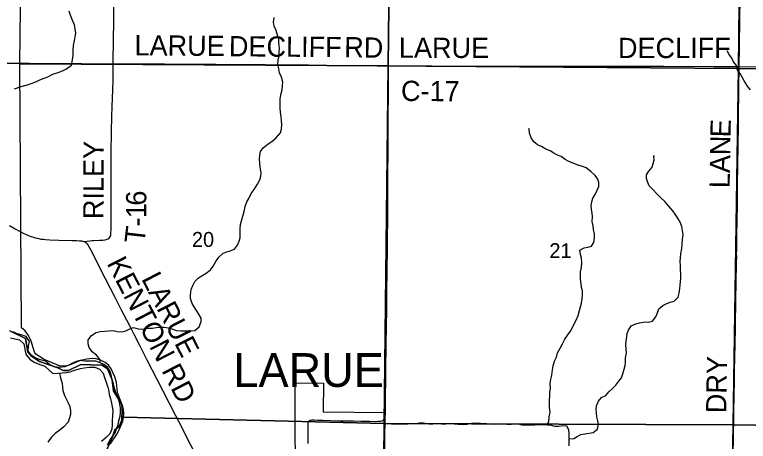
# Model space of a CAD drawing. Extents: x 1584893 to 1934202, y 663575 to 1091909.
# Drawn here: x 1718437 to 1729310, y 942730 to 949050 of the extents above; entities that cross this region are included whole.
import ezdxf

# ---------------------------------------------------------------- set-up
doc = ezdxf.new("R2010")
doc.units = 0
for name, color, linetype in [('GM_X_Corporation', 7, 'Continuous'), ('GM_X_Corporation_Text', 7, 'Continuous'), ('GM_X_County_Road', 7, 'Continuous'), ('GM_X_County_Road_Text', 7, 'Continuous'), ('GM_X_Major_River', 7, 'Continuous'), ('GM_X_Minor_River', 7, 'Continuous'), ('GM_X_Section', 7, 'Continuous'), ('GM_X_Section_Text', 7, 'Continuous'), ('GM_X_State_Route', 7, 'Continuous'), ('GM_X_Township', 7, 'Continuous'), ('GM_X_Township_Road', 7, 'Continuous'), ('GM_X_Township_Road_Text', 7, 'Continuous')]:
    doc.layers.add(name, color=color, linetype=linetype)

msp = doc.modelspace()

# ---------------------------------------------------------------- linework, layer by layer
at = {"layer": 'GM_X_Corporation'}
msp.add_lwpolyline([(1722603, 942161), (1722596, 942851), (1722595, 943595), (1723016, 943590), (1723008, 943168), (1723926, 943158), (1723924, 943078), (1723889, 940900)], dxfattribs=at)
at = {"layer": 'GM_X_County_Road'}
for points in [[(1723973, 948292), (1724028, 948292), (1724323, 948290), (1724536, 948289), (1725160, 948288), (1725635, 948288), (1725980, 948288), (1726258, 948287), (1726537, 948288), (1726849, 948288), (1727226, 948287), (1727521, 948286), (1727685, 948286), (1728063, 948285), (1728801, 948284), (1728981, 948283), (1729174, 948282)], [(1729174, 948282), (1729178, 948282), (1729604, 948276), (1729965, 948272), (1730293, 948266), (1730834, 948258), (1731014, 948255), (1731424, 948249), (1731884, 948243), (1732343, 948236), (1732523, 948235), (1732851, 948230), (1733195, 948225), (1733671, 948219), (1734294, 948211), (1734374, 948210)], [(1718362, 945929), (1718446, 945879), (1718517, 945837), (1718561, 945814), (1718606, 945793), (1718651, 945774), (1718682, 945762), (1718714, 945752), (1718746, 945743), (1718794, 945733), (1718826, 945727), (1718859, 945723), (1718892, 945720), (1718958, 945716), (1719089, 945711), (1719286, 945705), (1719352, 945704), (1719400, 945702), (1719433, 945698), (1719449, 945696), (1719464, 945692), (1719473, 945688)], [(1719473, 945688), (1719478, 945685), (1719491, 945677), (1719502, 945666), (1719512, 945654), (1719521, 945640), (1719561, 945569), (1719599, 945496), (1719709, 945276), (1719919, 944867), (1720015, 944680), (1720092, 944530), (1720152, 944414), (1720207, 944307), (1720287, 944152), (1720397, 943936), (1720542, 943652), (1720720, 943306), (1720820, 943114), (1720917, 942925), (1720999, 942764), (1721082, 942604), (1721194, 942384), (1721271, 942233)]]:
    msp.add_lwpolyline(points, dxfattribs=at)
at = {"layer": 'GM_X_Major_River'}
for points in [[(1718376, 944263), (1718439, 944246), (1718507, 944232), (1718571, 944175), (1718584, 944123), (1718592, 944065), (1718605, 944012), (1718661, 943946), (1718728, 943903), (1718808, 943870), (1718884, 943842), (1718945, 943789), (1719001, 943735), (1719071, 943738), (1719139, 943744), (1719203, 943747), (1719259, 943759), (1719309, 943778), (1719363, 943796), (1719413, 943810), (1719465, 943819), (1719543, 943829), (1719623, 943826), (1719693, 943799), (1719750, 943739), (1719770, 943676), (1719795, 943606), (1719820, 943532), (1719832, 943473), (1719837, 943423), (1719855, 943357), (1719872, 943295), (1719891, 943188), (1719887, 943104), (1719884, 943044), (1719884, 942978), (1719875, 942908), (1719847, 942840), (1719794, 942788), (1719724, 942727)], [(1719815, 942678), (1719856, 942764), (1719927, 942855), (1719953, 942925), (1719970, 942979), (1719982, 943035), (1720001, 943105), (1720007, 943159), (1720006, 943225), (1719992, 943310), (1719973, 943370), (1719938, 943451), (1719920, 943505), (1719901, 943583), (1719883, 943641), (1719872, 943692), (1719854, 943764), (1719811, 943828), (1719757, 943867), (1719705, 943891), (1719642, 943918), (1719590, 943918), (1719538, 943915), (1719476, 943919), (1719408, 943926), (1719350, 943910), (1719296, 943889), (1719242, 943859), (1719179, 943831), (1719097, 943822), (1719024, 943833), (1718954, 943867), (1718892, 943918), (1718821, 943937), (1718753, 943961), (1718683, 944008), (1718636, 944072), (1718644, 944142), (1718655, 944210), (1718608, 944283), (1718550, 944304), (1718466, 944328), (1718414, 944351)]]:
    msp.add_lwpolyline(points, dxfattribs=at)
at = {"layer": 'GM_X_Minor_River'}
for points in [[(1718435, 947952), (1718535, 947984), (1718589, 948000), (1718641, 948015), (1718697, 948035), (1718761, 948061), (1718811, 948083), (1718875, 948111), (1718927, 948131), (1719001, 948167), (1719081, 948195), (1719145, 948220), (1719205, 948248), (1719277, 948302), (1719296, 948380), (1719304, 948446), (1719304, 948521), (1719310, 948595), (1719323, 948661), (1719335, 948721), (1719341, 948777), (1719333, 948841), (1719322, 948901), (1719298, 948954), (1719270, 949026), (1719246, 949102)], [(1722355, 948439), (1722359, 948493), (1722361, 948555), (1722353, 948631), (1722350, 948688), (1722334, 948746), (1722312, 948814), (1722284, 948882), (1722272, 948940), (1722281, 949006)], [(1729343, 947938), (1729298, 947991), (1729249, 948068), (1729220, 948122), (1729189, 948177), (1729150, 948228), (1729135, 948296), (1729090, 948349), (1729065, 948406), (1729025, 948460), (1728996, 948513)], [(1719703, 943892), (1719706, 943935), (1719651, 944005), (1719585, 944055), (1719541, 944120), (1719525, 944176), (1719525, 944232), (1719574, 944300), (1719646, 944342), (1719702, 944358), (1719774, 944363), (1719828, 944365), (1719898, 944371), (1719954, 944359), (1720024, 944353), (1720086, 944368), (1720144, 944396), (1720200, 944414), (1720268, 944396), (1720332, 944392), (1720404, 944404), (1720482, 944407), (1720534, 944415), (1720600, 944419), (1720652, 944421), (1720714, 944413), (1720767, 944394), (1720837, 944374), (1720899, 944366), (1720973, 944366), (1721053, 944366), (1721109, 944371), (1721173, 944427), (1721202, 944503), (1721202, 944553), (1721166, 944616), (1721134, 944668), (1721096, 944724), (1721069, 944774), (1721045, 944845), (1721041, 944899), (1721051, 944981), (1721076, 945037), (1721106, 945095), (1721160, 945151), (1721224, 945191), (1721274, 945221), (1721340, 945271), (1721378, 945327), (1721417, 945393), (1721465, 945459), (1721527, 945515), (1721579, 945535), (1721633, 945554), (1721697, 945578), (1721741, 945634), (1721765, 945696), (1721778, 945746), (1721778, 945821), (1721780, 945877), (1721786, 945941), (1721800, 945997), (1721819, 946065), (1721839, 946133), (1721855, 946207), (1721879, 946277), (1721908, 946327), (1721944, 946399), (1721984, 946462), (1722034, 946538), (1722068, 946604), (1722087, 946656), (1722089, 946706), (1722077, 946792), (1722069, 946854), (1722065, 946904), (1722068, 946970), (1722078, 947025), (1722120, 947076), (1722192, 947138), (1722248, 947170), (1722310, 947220), (1722375, 947300), (1722393, 947356), (1722395, 947424), (1722393, 947479), (1722388, 947539), (1722376, 947605), (1722374, 947671), (1722372, 947731), (1722372, 947803), (1722385, 947882), (1722399, 947936), (1722407, 948000), (1722409, 948052), (1722392, 948126), (1722364, 948190), (1722350, 948250), (1722338, 948319), (1722340, 948377), (1722355, 948439)], [(1726324, 942969), (1726353, 943020), (1726360, 943092), (1726371, 943164), (1726366, 943231), (1726363, 943291), (1726366, 943347), (1726367, 943399), (1726370, 943459), (1726377, 943511), (1726374, 943587), (1726383, 943649), (1726400, 943709), (1726408, 943791), (1726417, 943849), (1726440, 943919), (1726465, 943977), (1726482, 944042), (1726521, 944110), (1726558, 944176), (1726593, 944241), (1726636, 944305), (1726677, 944360), (1726710, 944426), (1726735, 944481), (1726762, 944537), (1726787, 944595), (1726806, 944669), (1726840, 944776), (1726847, 944836), (1726853, 944910), (1726851, 944960), (1726840, 945011), (1726831, 945065), (1726824, 945131), (1726823, 945183), (1726822, 945240), (1726837, 945305), (1726842, 945378), (1726837, 945444), (1726824, 945498), (1726813, 945560), (1726876, 945597), (1726934, 945607), (1726986, 945620), (1727023, 945675), (1727032, 945745), (1727031, 945801), (1727014, 945870), (1727011, 945920), (1726996, 945988), (1727000, 946054), (1726994, 946111), (1726985, 946171), (1726982, 946221), (1726989, 946279), (1727008, 946331), (1727041, 946385), (1727072, 946450), (1727093, 946504), (1727094, 946562), (1727081, 946612), (1727038, 946669), (1726977, 946728), (1726909, 946780), (1726852, 946801), (1726774, 946826), (1726716, 946849), (1726649, 946876), (1726597, 946905), (1726538, 946948), (1726484, 946969), (1726430, 946998), (1726371, 947033), (1726311, 947058), (1726244, 947095), (1726188, 947124), (1726133, 947167), (1726092, 947226), (1726069, 947293), (1726060, 947359), (1726050, 947357)], [(1726655, 942767), (1726723, 942774), (1726776, 942801), (1726826, 942830), (1726885, 942843), (1727013, 942861), (1727074, 942912), (1727089, 942982), (1727078, 943034), (1727065, 943095), (1727060, 943153), (1727057, 943203), (1727060, 943257), (1727089, 943327), (1727136, 943380), (1727200, 943409), (1727241, 943461), (1727292, 943506), (1727345, 943563), (1727390, 943621), (1727429, 943672), (1727448, 943728), (1727469, 943798), (1727484, 943852), (1727489, 943902), (1727492, 943966), (1727503, 944034), (1727498, 944094), (1727493, 944158), (1727498, 944220), (1727509, 944274), (1727514, 944326), (1727535, 944378), (1727576, 944441), (1727642, 944470), (1727698, 944483), (1727783, 944498), (1727833, 944497), (1727891, 944510), (1727938, 944572), (1727965, 944635), (1727986, 944693), (1728041, 944740), (1728094, 944766), (1728152, 944789), (1728210, 944806), (1728269, 944863), (1728284, 944925), (1728294, 944993), (1728300, 945045), (1728305, 945095), (1728312, 945149), (1728309, 945213), (1728304, 945275), (1728303, 945335), (1728300, 945394), (1728305, 945450), (1728312, 945508), (1728325, 945584), (1728330, 945648), (1728336, 945724), (1728343, 945790), (1728336, 945852), (1728327, 945910), (1728298, 945975), (1728267, 946036), (1728226, 946094), (1728192, 946145), (1728128, 946216), (1728071, 946283), (1728013, 946338), (1727954, 946398), (1727901, 946455), (1727842, 946514), (1727821, 946564), (1727802, 946623), (1727803, 946677), (1727834, 946734), (1727885, 946790), (1727902, 946843), (1727913, 946901), (1727909, 946951), (1727918, 946965)], [(1719099, 943740), (1719114, 943670), (1719139, 943587), (1719145, 943535), (1719153, 943481), (1719176, 943408), (1719205, 943350), (1719231, 943298), (1719253, 943247), (1719266, 943183), (1719265, 943125), (1719229, 943015), (1719164, 942943), (1719110, 942900), (1719035, 942848), (1718983, 942793), (1718926, 942717)], [(1723979, 942997), (1724049, 942985), (1724121, 942987), (1724185, 942987), (1724265, 942988), (1724321, 942992), (1724375, 942996), (1724439, 943004), (1724497, 943004), (1724573, 942991), (1724635, 942989), (1724701, 942993), (1724765, 942991), (1724827, 942991), (1724881, 942992), (1724953, 942990), (1725009, 942982), (1725077, 942978), (1725143, 942986), (1725207, 942997), (1725277, 943003), (1725411, 942992)], [(1726653, 942665), (1726657, 942737), (1726653, 942787), (1726656, 942845), (1726651, 942899), (1726622, 942954), (1726562, 942961), (1726496, 942952), (1726446, 942951), (1726394, 942964), (1726334, 942969), (1726268, 942974), (1726216, 942972), (1726146, 942970), (1726094, 942970), (1726028, 942970), (1725956, 942967), (1725902, 942982), (1725850, 942989), (1725796, 942981), (1725729, 942980), (1725677, 942983), (1725623, 942984), (1725557, 942981), (1725495, 942986), (1725431, 942989), (1725411, 942992)]]:
    msp.add_lwpolyline(points, dxfattribs=at)
at = {"layer": 'GM_X_Section'}
for points in [[(1718577, 953608), (1724030, 953572), (1723973, 948294), (1718513, 948322)], [(1724030, 953572), (1729219, 953534), (1729163, 948254), (1723973, 948294)], [(1729219, 953534), (1734432, 953454), (1734388, 948198), (1729163, 948254)], [(1718513, 948322), (1723973, 948294), (1723914, 942992), (1720049, 943086), (1720057, 943138), (1720052, 943202), (1720036, 943254), (1719960, 943451), (1719944, 943601), (1719923, 943685), (1719866, 943806), (1719831, 943854), (1719777, 943899), (1719707, 943933), (1719644, 943954), (1719596, 943958), (1719508, 943949), (1719415, 943928), (1719296, 943878), (1719259, 943862), (1719210, 943850), (1719110, 943841), (1718873, 943944), (1718752, 944021), (1718729, 944053), (1718680, 944216), (1718641, 944300), (1718590, 944369), (1718536, 944413)], [(1723973, 948294), (1729163, 948254), (1729088, 942976), (1723914, 942992)], [(1729163, 948254), (1734388, 948198), (1734314, 942896), (1729088, 942976)]]:
    msp.add_lwpolyline(points, close=True, dxfattribs=at)
for points in [[(1719851, 942688), (1719946, 942827), (1719983, 942892), (1720038, 943028), (1720049, 943086), (1723914, 942992), (1723863, 937892)], [(1723863, 937892), (1723914, 942992), (1729088, 942976), (1729008, 938438)], [(1729316, 938638), (1729277, 938630), (1729255, 938608), (1729209, 938549), (1729120, 938463), (1729088, 938452), (1729008, 938438), (1729088, 942976), (1734314, 942896)]]:
    msp.add_lwpolyline(points, dxfattribs=at)
at = {"layer": 'GM_X_State_Route'}
for points in [[(1723979, 949123), (1723978, 948992), (1723975, 948697), (1723974, 948418), (1723973, 948292)], [(1723973, 948292), (1723973, 948268), (1723972, 948107), (1723970, 947906), (1723970, 947788), (1723969, 947631), (1723968, 947422), (1723968, 947297), (1723967, 947190), (1723967, 947053), (1723966, 946919), (1723965, 946794), (1723964, 946563), (1723962, 946351), (1723962, 946123), (1723961, 945974), (1723959, 945777), (1723956, 945548), (1723953, 945302), (1723951, 945171), (1723949, 945023), (1723946, 944695), (1723942, 944416), (1723938, 944186), (1723936, 944055), (1723935, 943890), (1723933, 943645), (1723930, 943383), (1723926, 943158)], [(1723924, 943078), (1723918, 943065), (1723913, 943057), (1723901, 943045), (1723886, 943034), (1723877, 943031), (1723860, 943026), (1723841, 943023), (1723818, 943022), (1723779, 943020), (1723696, 943022), (1723567, 943024), (1723460, 943027), (1723269, 943031), (1723121, 943034), (1723006, 943038), (1722924, 943040), (1722875, 943042), (1722859, 943042), (1722843, 943041), (1722828, 943040), (1722813, 943036), (1722805, 943033), (1722798, 943028), (1722791, 943019), (1722786, 943009), (1722783, 942999)], [(1723926, 943158), (1723925, 943113), (1723924, 943078)], [(1722783, 942999), (1722782, 942994), (1722780, 942978), (1722780, 942962), (1722781, 942913), (1722782, 942826), (1722783, 942771), (1722783, 942700)]]:
    msp.add_lwpolyline(points, dxfattribs=at)
at = {"layer": 'GM_X_Township'}
for points in [[(1718363, 944365), (1718598, 944251), (1718631, 944058), (1718688, 943990), (1718804, 943910), (1719079, 943820), (1719158, 943779), (1719237, 943778), (1719417, 943868), (1719736, 943858), (1719812, 943804), (1719881, 943642), (1719903, 943476), (1720024, 943273), (1720030, 943209), (1720024, 943042), (1719981, 942947), (1719920, 942898), (1719885, 942796), (1719752, 942495)], [(1719752, 942495), (1719885, 942796), (1719920, 942898), (1719981, 942947), (1720024, 943042), (1720030, 943209), (1720024, 943273), (1719903, 943476), (1719881, 943642), (1719812, 943804), (1719736, 943858), (1719417, 943868), (1719237, 943778), (1719158, 943779), (1719079, 943820), (1718804, 943910), (1718688, 943990), (1718631, 944058), (1718598, 944251), (1718363, 944365)]]:
    msp.add_lwpolyline(points, dxfattribs=at)
at = {"layer": 'GM_X_Township_Road'}
for points in [[(1729174, 948282), (1729174, 948294), (1729174, 948326), (1729178, 948522), (1729179, 948620), (1729183, 948949), (1729187, 949326), (1729188, 949457), (1729188, 949539), (1729189, 949605), (1729190, 949703), (1729190, 949736), (1729190, 949769), (1729190, 949834), (1729191, 949884), (1729193, 950179), (1729194, 950310), (1729195, 950359), (1729196, 950540), (1729197, 950589), (1729198, 950720), (1729199, 950884), (1729200, 950917)], [(1719898, 948324), (1719903, 948707), (1719905, 948920), (1719908, 949166)], [(1715895, 948343), (1715931, 948341), (1715997, 948339), (1716194, 948338), (1716506, 948337), (1716686, 948337), (1716899, 948337), (1717096, 948336), (1717786, 948335), (1717999, 948334), (1718245, 948333), (1718458, 948330), (1718655, 948330), (1718951, 948329), (1719427, 948327), (1719898, 948324)], [(1719473, 945688), (1719513, 945694), (1719553, 945701), (1719580, 945704), (1719613, 945706), (1719695, 945709), (1719744, 945712), (1719777, 945715), (1719794, 945718), (1719810, 945723), (1719825, 945730), (1719838, 945740), (1719848, 945754), (1719856, 945769), (1719860, 945785), (1719862, 945802), (1719865, 945884), (1719866, 945933), (1719866, 946114), (1719866, 946459), (1719865, 946557), (1719865, 946656), (1719866, 946803), (1719869, 947000), (1719873, 947312), (1719879, 947542), (1719884, 947689), (1719892, 947935), (1719895, 948083), (1719898, 948313), (1719898, 948324)], [(1719898, 948324), (1719935, 948324), (1720231, 948322), (1720461, 948321), (1720658, 948321), (1721018, 948319), (1721166, 948320), (1721675, 948314), (1721921, 948312), (1722151, 948311), (1722331, 948309), (1722479, 948306), (1722676, 948306), (1722791, 948305), (1723184, 948299), (1723496, 948297), (1723660, 948295), (1723808, 948294), (1723973, 948292)], [(1729121, 944590), (1729123, 944685), (1729127, 944898), (1729130, 945013), (1729132, 945170), (1729134, 945285), (1729136, 945377), (1729138, 945472), (1729137, 945505), (1729139, 945570), (1729142, 945784), (1729148, 946227), (1729151, 946555), (1729155, 946801), (1729160, 947129), (1729163, 947392), (1729166, 947605), (1729170, 947851), (1729169, 947933), (1729169, 947982), (1729170, 948032), (1729174, 948212), (1729174, 948261), (1729174, 948282)], [(1729095, 943015), (1729097, 943126), (1729097, 943175), (1729105, 943635), (1729107, 943799), (1729110, 943946), (1729115, 944193), (1729119, 944389), (1729121, 944553), (1729121, 944590)], [(1723912, 942213), (1723913, 942295), (1723916, 942409), (1723917, 942622), (1723921, 942852), (1723922, 942949), (1723924, 943078)], [(1729054, 940378), (1729054, 940454), (1729054, 940518), (1729057, 940716), (1729059, 940896), (1729061, 941009), (1729064, 941208), (1729067, 941415), (1729069, 941504), (1729075, 941751), (1729077, 941855), (1729079, 942002), (1729081, 942152), (1729084, 942303), (1729086, 942473), (1729087, 942572), (1729088, 942621), (1729089, 942703), (1729090, 942802), (1729091, 942868), (1729095, 943015)]]:
    msp.add_lwpolyline(points, dxfattribs=at)

# ---------------------------------------------------------------- texts
at = {"layer": 'GM_X_Corporation_Text'}
msp.add_text('LARUE', height=500, rotation=0, dxfattribs=at).set_placement((1721679, 943536))
at = {"layer": 'GM_X_County_Road_Text'}
for s, rotation, p in [('LARUE', 359.7964, (1724131, 948412)), ('DECLIFF', 0, (1727378, 948407)), ('C-17', 359.6489, (1724162, 947772)), ('KENTON RD', 297.0983, (1719797, 945368)), ('LARUE', 297.1122, (1720310, 945139))]:
    msp.add_text(s, height=300, rotation=rotation, dxfattribs=at).set_placement(p)
at = {"layer": 'GM_X_Section_Text'}
for s, p in [('20', (1721064, 945610)), ('21', (1726362, 945444))]:
    msp.add_text(s, height=221, rotation=0, dxfattribs=at).set_placement(p)
at = {"layer": 'GM_X_Township_Road_Text'}
for s, rotation, p in [('LARUE', 359.5897, (1720212, 948447)), ('DECLIFF', 359.5095, (1721611, 948434)), ('RD', 359.0164, (1723319, 948420)), ('E', 88.3755, (1729045, 947229)), ('N', 89.1548, (1729042, 946966)), ('RILEY', 89.7692, (1719753, 946021)), ('A', 89.1731, (1729038, 946702)), ('L', 89.1728, (1729034, 946478)), ('6', 89.9923, (1720388, 946221)), ('1', 89.9271, (1720388, 946036)), ('-', 90.2954, (1720388, 945913)), ('T', 83.5538, (1720361, 945652)), ('DRY', 89.0355, (1728982, 943144))]:
    msp.add_text(s, height=300, rotation=rotation, dxfattribs=at).set_placement(p)

doc.saveas('drawing.dxf')
